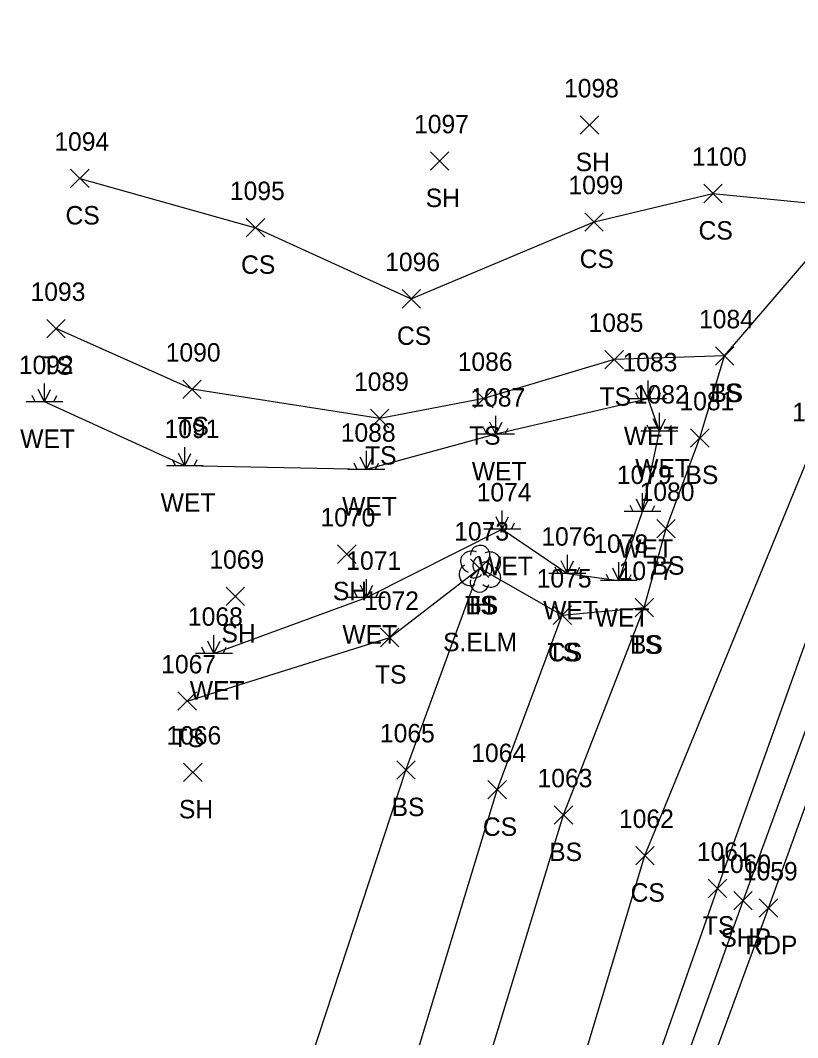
# Model space of a CAD drawing. Extents: x 1554917 to 1555870, y 813367 to 816333.
# Drawn here: x 1554922.1 to 1555006.4, y 813476.5 to 813586.9 of the extents above; entities that cross this region are included whole.
import ezdxf

# ---------------------------------------------------------------- set-up
doc = ezdxf.new("R2010")
doc.units = 0
for name, color, linetype in [('L_A', 7, 'Continuous'), ('L_C', 7, 'Continuous'), ('L_I', 7, 'Continuous'), ('L_TIC', 7, 'Continuous'), ('LELB', 7, 'Continuous'), ('LTD', 7, 'Continuous'), ('LWET', 7, 'Continuous'), ('P_A', 7, 'Continuous'), ('P_I', 7, 'Continuous'), ('P_TIC', 7, 'Continuous'), ('PET', 7, 'Continuous'), ('PSP', 7, 'Continuous')]:
    doc.layers.add(name, color=color, linetype=linetype)

msp = doc.modelspace()

# ---------------------------------------------------------------- linework, layer by layer
at = {"layer": 'L_TIC'}
for points in [[(1554982.79, 813574.5), (1554984.79, 813576.5)], [(1554984.79, 813574.5), (1554982.79, 813576.5)], [(1554966.53, 813570.61), (1554968.53, 813572.61)], [(1554968.53, 813570.61), (1554966.53, 813572.61)], [(1554927.52, 813568.72), (1554929.52, 813570.72)], [(1554929.52, 813568.72), (1554927.52, 813570.72)], [(1554996.17, 813567.08), (1554998.17, 813569.08)], [(1554998.17, 813567.08), (1554996.17, 813569.08)], [(1554946.56, 813563.37), (1554948.56, 813565.37)], [(1554948.56, 813563.37), (1554946.56, 813565.37)], [(1554983.28, 813564), (1554985.28, 813566)], [(1554985.28, 813564), (1554983.28, 813566)], [(1554963.46, 813555.66), (1554965.46, 813557.66)], [(1554965.46, 813555.66), (1554963.46, 813557.66)], [(1554924.94, 813552.43), (1554926.94, 813554.43)], [(1554926.94, 813552.43), (1554924.94, 813554.43)], [(1554985.46, 813549.07), (1554987.46, 813551.07)], [(1554987.46, 813549.07), (1554985.46, 813551.07)], [(1554997.43, 813549.46), (1554999.43, 813551.46)], [(1554999.43, 813549.46), (1554997.43, 813551.46)], [(1554997.43, 813549.46), (1554999.43, 813551.46)], [(1554999.43, 813549.46), (1554997.43, 813551.46)], [(1554939.68, 813545.85), (1554941.68, 813547.85)], [(1554941.68, 813545.85), (1554939.68, 813547.85)], [(1554971.32, 813544.84), (1554973.32, 813546.84)], [(1554973.32, 813544.84), (1554971.32, 813546.84)], [(1554960.03, 813542.68), (1554962.03, 813544.68)], [(1554962.03, 813542.68), (1554960.03, 813544.68)], [(1554994.75, 813540.57), (1554996.75, 813542.57)], [(1554996.75, 813540.57), (1554994.75, 813542.57)], [(1554991.08, 813530.74), (1554993.08, 813532.74)], [(1554993.08, 813530.74), (1554991.08, 813532.74)], [(1554956.47, 813527.97), (1554958.47, 813529.97)], [(1554958.47, 813527.97), (1554956.47, 813529.97)], [(1554970.88, 813526.44), (1554972.88, 813528.44)], [(1554972.88, 813526.44), (1554970.88, 813528.44)], [(1554970.88, 813526.44), (1554972.88, 813528.44)], [(1554972.88, 813526.44), (1554970.88, 813528.44)], [(1554944.39, 813523.39), (1554946.39, 813525.39)], [(1554946.39, 813523.39), (1554944.39, 813525.39)], [(1554979.83, 813521.35), (1554981.83, 813523.35)], [(1554981.83, 813521.35), (1554979.83, 813523.35)], [(1554979.83, 813521.35), (1554981.83, 813523.35)], [(1554981.83, 813521.35), (1554979.83, 813523.35)], [(1554988.73, 813522.17), (1554990.73, 813524.17)], [(1554990.73, 813522.17), (1554988.73, 813524.17)], [(1554988.73, 813522.17), (1554990.73, 813524.17)], [(1554990.73, 813522.17), (1554988.73, 813524.17)], [(1554961.12, 813518.93), (1554963.12, 813520.93)], [(1554963.12, 813518.93), (1554961.12, 813520.93)], [(1554939.16, 813512.04), (1554941.16, 813514.04)], [(1554941.16, 813512.04), (1554939.16, 813514.04)], [(1554939.77, 813504.32), (1554941.77, 813506.32)], [(1554941.77, 813504.32), (1554939.77, 813506.32)], [(1554962.88, 813504.56), (1554964.88, 813506.56)], [(1554964.88, 813504.56), (1554962.88, 813506.56)], [(1554972.77, 813502.42), (1554974.77, 813504.42)], [(1554974.77, 813502.42), (1554972.77, 813504.42)], [(1554979.97, 813499.69), (1554981.97, 813501.69)], [(1554981.97, 813499.69), (1554979.97, 813501.69)], [(1554988.8, 813495.28), (1554990.8, 813497.28)], [(1554990.8, 813495.28), (1554988.8, 813497.28)], [(1554996.67, 813491.71), (1554998.67, 813493.71)], [(1554998.67, 813491.71), (1554996.67, 813493.71)]]:
    msp.add_lwpolyline(points, dxfattribs=at)
at = {"layer": 'LELB'}
for points in [[(1554960.86, 813387.22), (1554975.88, 813430.61), (1554997.67, 813492.71), (1555013.89, 813538.05), (1555028.68, 813579.18), (1555048.82, 813626.54), (1555068.18, 813674.18), (1555096.05, 813749.22), (1555111.01, 813785.1), (1555115.51, 813798.83), (1555119.3, 813812.87), (1555134.87, 813853.17), (1555141.95, 813870.8), (1555155.34, 813907.69), (1555153.32, 813917.67), (1555161.57, 813925.65), (1555168.92, 813938.89)], [(1554955.97, 813389.51), (1554961.01, 813406.77), (1554970.65, 813432.6), (1554989.8, 813496.28), (1555007.9, 813540.38), (1555025.82, 813579.85), (1555048.82, 813626.54)], [(1554928.52, 813569.72), (1554947.56, 813564.37), (1554964.46, 813556.66), (1554984.28, 813565), (1554997.17, 813568.08), (1555012.26, 813566.6), (1555009.99, 813588.02), (1555015.55, 813603.36), (1555029.3, 813621.81)], [(1554957.39, 813409.71), (1554960.72, 813434.3), (1554980.97, 813500.69), (1554989.73, 813523.17), (1554992.08, 813531.74), (1554995.75, 813541.57), (1554998.43, 813550.46), (1555012.26, 813566.6), (1555019.54, 813585.69), (1555024.77, 813597.99)], [(1554998.43, 813550.46), (1554986.46, 813550.07), (1554972.32, 813545.84), (1554961.03, 813543.68), (1554940.68, 813546.85), (1554925.94, 813553.43)], [(1554931.85, 813420.03), (1554941.76, 813438.17), (1554963.88, 813505.56), (1554971.88, 813527.44)], [(1554940.16, 813513.04), (1554962.12, 813519.93), (1554971.88, 813527.44), (1554980.83, 813522.35), (1554989.73, 813523.17)], [(1554948.44, 813415.56), (1554953.29, 813436.01), (1554973.77, 813503.42), (1554980.83, 813522.35)]]:
    msp.add_lwpolyline(points, dxfattribs=at)
at = {"layer": 'LTD'}
msp.add_line((1554971.88, 813527.44), (1554971.88, 813527.44), dxfattribs=at)
msp.add_line((1554971.88, 813527.44), (1554971.88, 813527.44), dxfattribs=at)
msp.add_arc((1554971.93, 813528.87), 1.05, 335.5272, 180.9563, dxfattribs=at)
for centre, major_axis, ratio, start_param, end_param in [((1554971.09, 813528.1), (1.21, -0.51), 0.895232, 1.570796, 4.712389), ((1554972.92, 813528.02), (-1.14, -0.48), 0.949671, 1.570796, 4.712389), ((1554970.8, 813526.73), (0.58, -1.04), 0.959034, 3.141593, 6.283185), ((1554971.67, 813527.9), (-0.208, -0.792), 0.645439, 3.141593, 6.283185), ((1554972.38, 813527.27), (-0.5, 0.667), 0.989748, 3.141593, 6.283185), ((1554971.42, 813526.69), (-0.625, -0.083), 0.423636, 0, 3.141593), ((1554972.88, 813526.6), (-1.09, 0.79), 0.841452, 1.570796, 4.712389), ((1554971.88, 813525.94), (0.26, 1.06), 0.942809, 1.570796, 4.712389)]:
    msp.add_ellipse(centre, major_axis=major_axis, ratio=ratio, start_param=start_param, end_param=end_param, dxfattribs=at)
at = {"layer": 'LWET'}
for p, q in [((1554990.13, 813545.8), (1554990.13, 813547.8)), ((1554924.68, 813545.49), (1554924.01, 813546.83)), ((1554924.68, 813545.49), (1554924.68, 813547.49)), ((1554924.68, 813545.49), (1554925.34, 813546.83)), ((1554989.13, 813545.8), (1554988.8, 813546.47)), ((1554990.13, 813545.8), (1554989.47, 813547.14)), ((1554990.13, 813545.8), (1554990.8, 813547.14)), ((1554991.13, 813545.8), (1554991.47, 813546.47)), ((1554926.68, 813545.49), (1554922.68, 813545.49)), ((1554923.68, 813545.49), (1554923.34, 813546.16)), ((1554925.68, 813545.49), (1554926.01, 813546.16)), ((1554992.13, 813545.8), (1554988.13, 813545.8)), ((1554991.36, 813542.3), (1554991.36, 813544.3)), ((1554973.64, 813541.97), (1554972.98, 813543.3)), ((1554973.64, 813541.97), (1554973.64, 813543.97)), ((1554973.64, 813541.97), (1554974.31, 813543.3)), ((1554991.36, 813542.3), (1554990.69, 813543.63)), ((1554991.36, 813542.3), (1554992.03, 813543.63)), ((1554972.64, 813541.97), (1554972.31, 813542.64)), ((1554974.64, 813541.97), (1554974.98, 813542.64)), ((1554993.36, 813542.3), (1554989.36, 813542.3)), ((1554990.36, 813542.3), (1554990.03, 813542.96)), ((1554992.36, 813542.3), (1554992.69, 813542.96)), ((1554975.64, 813541.97), (1554971.64, 813541.97)), ((1554939.9, 813538.56), (1554939.23, 813539.89)), ((1554939.9, 813538.56), (1554939.9, 813540.56)), ((1554939.9, 813538.56), (1554940.57, 813539.89)), ((1554959.59, 813538.16), (1554959.59, 813540.16)), ((1554938.9, 813538.56), (1554938.57, 813539.23)), ((1554940.9, 813538.56), (1554941.23, 813539.23)), ((1554958.59, 813538.16), (1554958.25, 813538.83)), ((1554959.59, 813538.16), (1554958.92, 813539.5)), ((1554959.59, 813538.16), (1554960.25, 813539.5)), ((1554960.59, 813538.16), (1554960.92, 813538.83)), ((1554941.9, 813538.56), (1554937.9, 813538.56)), ((1554961.59, 813538.16), (1554957.59, 813538.16)), ((1554989.53, 813533.58), (1554989.53, 813535.58)), ((1554989.53, 813533.58), (1554988.87, 813534.92)), ((1554989.53, 813533.58), (1554990.2, 813534.92)), ((1554974.33, 813531.69), (1554974.33, 813533.69)), ((1554991.53, 813533.58), (1554987.53, 813533.58)), ((1554988.53, 813533.58), (1554988.2, 813534.25)), ((1554990.53, 813533.58), (1554990.87, 813534.25)), ((1554973.33, 813531.69), (1554972.99, 813532.36)), ((1554974.33, 813531.69), (1554973.66, 813533.02)), ((1554974.33, 813531.69), (1554974.99, 813533.02)), ((1554975.33, 813531.69), (1554975.66, 813532.36)), ((1554976.33, 813531.69), (1554972.33, 813531.69)), ((1554981.39, 813526.89), (1554981.39, 813528.89)), ((1554981.39, 813526.89), (1554980.72, 813528.23)), ((1554981.39, 813526.89), (1554982.05, 813528.23)), ((1554986.97, 813526.11), (1554986.97, 813528.11)), ((1554983.39, 813526.89), (1554979.39, 813526.89)), ((1554980.39, 813526.89), (1554980.05, 813527.56)), ((1554982.39, 813526.89), (1554982.72, 813527.56)), ((1554985.97, 813526.11), (1554985.64, 813526.77)), ((1554986.97, 813526.11), (1554986.31, 813527.44)), ((1554986.97, 813526.11), (1554987.64, 813527.44)), ((1554987.97, 813526.11), (1554988.31, 813526.77)), ((1554959.61, 813524.27), (1554958.95, 813525.61)), ((1554959.61, 813524.27), (1554959.61, 813526.27)), ((1554959.61, 813524.27), (1554960.28, 813525.61)), ((1554988.97, 813526.11), (1554984.97, 813526.11)), ((1554958.61, 813524.27), (1554958.28, 813524.94)), ((1554960.61, 813524.27), (1554960.95, 813524.94)), ((1554961.61, 813524.27), (1554957.61, 813524.27)), ((1554943.06, 813518.2), (1554943.06, 813520.2)), ((1554942.06, 813518.2), (1554941.73, 813518.87)), ((1554943.06, 813518.2), (1554942.39, 813519.54)), ((1554943.06, 813518.2), (1554943.73, 813519.54)), ((1554944.06, 813518.2), (1554944.39, 813518.87)), ((1554945.06, 813518.2), (1554941.06, 813518.2))]:
    msp.add_line(p, q, dxfattribs=at)
msp.add_lwpolyline([(1554943.06, 813518.2), (1554959.61, 813524.27), (1554974.33, 813531.69), (1554981.39, 813526.89), (1554986.97, 813526.11), (1554989.53, 813533.58), (1554991.36, 813542.3), (1554990.13, 813545.8), (1554973.64, 813541.97), (1554959.59, 813538.16), (1554939.9, 813538.56), (1554924.68, 813545.49)], dxfattribs=at)
at = {"layer": 'P_TIC'}
for points in [[(1554999.44, 813490.39), (1555001.44, 813492.39)], [(1555001.44, 813490.39), (1554999.44, 813492.39)], [(1555002.19, 813489.59), (1555004.19, 813491.59)], [(1555004.19, 813489.59), (1555002.19, 813491.59)]]:
    msp.add_lwpolyline(points, dxfattribs=at)
at = {"layer": 'PET'}
msp.add_lwpolyline([(1554965.43, 813385.56), (1554980.95, 813429.92), (1555003.19, 813490.59), (1555019.55, 813535.73), (1555035.2, 813576.47), (1555053.52, 813624.76), (1555072.33, 813672.52), (1555101.11, 813747.71), (1555125.53, 813809.89), (1555141.72, 813851.12), (1555161.36, 813900.53), (1555183.5, 813956.99)], dxfattribs=at)
at = {"layer": 'PSP'}
msp.add_lwpolyline([(1554963, 813386.3), (1554978.53, 813430.4), (1555000.44, 813491.39), (1555017.18, 813537.03), (1555032.55, 813577.93), (1555050.86, 813625.69), (1555069.49, 813673.81), (1555098.21, 813748.28), (1555122.69, 813810.6), (1555138.9, 813851.92), (1555160.79, 813906.47), (1555173.05, 813937.33)], dxfattribs=at)

# ---------------------------------------------------------------- texts
at = {"layer": 'L_A'}
for s, p in [('SH', (1554982.28, 813570.5)), ('SH', (1554966.02, 813566.61)), ('CS', (1554926.96, 813564.72)), ('CS', (1554995.61, 813563.08)), ('CS', (1554982.72, 813560)), ('CS', (1554946, 813559.37)), ('CS', (1554962.9, 813551.66)), ('TS', (1554924.35, 813548.43)), ('TS', (1554984.87, 813545.07)), ('TS', (1554996.84, 813545.46)), ('BS', (1554996.87, 813545.46)), ('TS', (1554939.09, 813541.85)), ('WET', (1554922.05, 813540.49)), ('TS', (1554970.73, 813540.84)), ('WET', (1554987.51, 813540.8)), ('TS', (1554959.44, 813538.68)), ('WET', (1554971.02, 813536.97)), ('WET', (1554988.74, 813537.3)), ('BS', (1554994.19, 813536.57)), ('WET', (1554937.28, 813533.56)), ('WET', (1554956.96, 813533.16)), ('WET', (1554986.91, 813528.58)), ('WET', (1554971.7, 813526.69)), ('BS', (1554990.52, 813526.74)), ('SH', (1554955.96, 813523.97)), ('TS', (1554970.29, 813522.44)), ('BS', (1554970.32, 813522.44)), ('H', (1554971.32, 813522.44)), ('WET', (1554978.76, 813521.89)), ('WET', (1554984.35, 813521.11)), ('SH', (1554943.88, 813519.39)), ('WET', (1554956.99, 813519.27)), ('TS', (1554988.14, 813518.17)), ('BS', (1554988.17, 813518.17)), ('TS', (1554979.24, 813517.35)), ('CS', (1554979.27, 813517.35)), ('TS', (1554960.52, 813514.93)), ('WET', (1554940.44, 813513.2)), ('TS', (1554938.57, 813508.04)), ('SH', (1554939.26, 813500.32)), ('BS', (1554962.32, 813500.56)), ('CS', (1554972.22, 813498.42)), ('BS', (1554979.41, 813495.69)), ('CS', (1554988.24, 813491.28)), ('TS', (1554996.08, 813487.71))]:
    msp.add_text(s, height=2, dxfattribs=at).set_placement(p)
at = {"layer": 'L_C'}
msp.add_text('S.ELM', height=2, dxfattribs=at).set_placement((1554967.91, 813518.44))
at = {"layer": 'L_I'}
for s, p in [('1098', (1554981.02, 813578.5)), ('1097', (1554964.76, 813574.61)), ('1094', (1554925.75, 813572.72)), ('1100', (1554994.88, 813571.08)), ('1099', (1554981.5, 813568)), ('1095', (1554944.79, 813567.37)), ('1096', (1554961.63, 813559.66)), ('1093', (1554923.17, 813556.43)), ('1084', (1554995.66, 813553.46)), ('1084', (1554995.66, 813553.46)), ('1085', (1554983.68, 813553.07)), ('1090', (1554937.83, 813549.85)), ('1086', (1554969.49, 813548.84)), ('1092', (1554921.9, 813548.49)), ('1083', (1554987.36, 813548.8)), ('1089', (1554958.25, 813546.68)), ('1087', (1554970.87, 813544.97)), ('1082', (1554988.59, 813545.3)), ('1081', (1554993.54, 813544.57)), ('1129', (1555005.77, 813543.38)), ('1091', (1554937.7, 813541.56)), ('1088', (1554956.81, 813541.16)), ('1079', (1554986.75, 813536.58)), ('1074', (1554971.55, 813534.69)), ('1080', (1554989.22, 813534.74)), ('1070', (1554954.61, 813531.97)), ('1073', (1554969.11, 813530.44)), ('1073', (1554969.11, 813530.44)), ('1073', (1554969.11, 813530.44)), ('1076', (1554978.56, 813529.89)), ('1078', (1554984.2, 813529.11)), ('1069', (1554942.56, 813527.39)), ('1071', (1554957.41, 813527.27)), ('1077', (1554986.95, 813526.17)), ('1077', (1554986.95, 813526.17)), ('1075', (1554978.06, 813525.35)), ('1075', (1554978.06, 813525.35)), ('1072', (1554959.34, 813522.93)), ('1068', (1554940.24, 813521.2)), ('1067', (1554937.34, 813516.04)), ('1066', (1554937.9, 813508.32)), ('1065', (1554961.06, 813508.56)), ('1064', (1554970.96, 813506.42)), ('1063', (1554978.15, 813503.69)), ('1062', (1554986.98, 813499.28)), ('1061', (1554995.42, 813495.71))]:
    msp.add_text(s, height=2, dxfattribs=at).set_placement(p)
at = {"layer": 'P_A'}
for s, p in [('SHP', (1554997.97, 813486.39)), ('RDP', (1555000.68, 813485.59))]:
    msp.add_text(s, height=2, dxfattribs=at).set_placement(p)
at = {"layer": 'P_I'}
for s, p in [('1060', (1554997.53, 813494.39)), ('1059', (1555000.41, 813493.59))]:
    msp.add_text(s, height=2, dxfattribs=at).set_placement(p)

doc.saveas('drawing.dxf')
